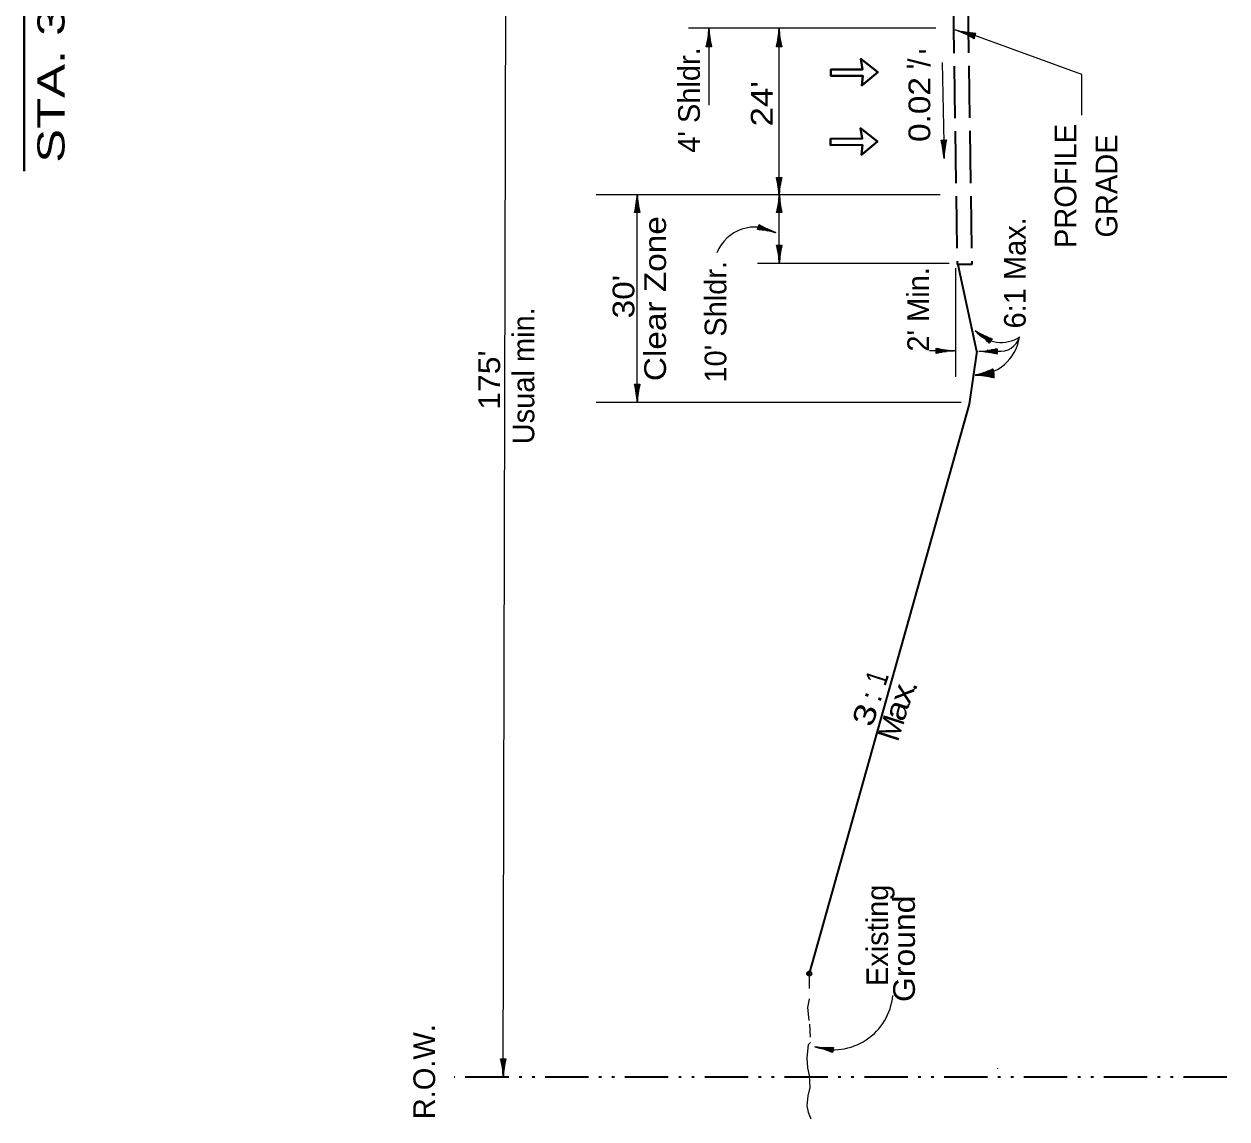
# Model space of a CAD drawing. Extents: x 2363427 to 2368559, y 6957299 to 6980140.
# Drawn here: x 2364444 to 2365220, y 6962821 to 6963528 of the extents above; entities that cross this region are included whole.
import ezdxf
from ezdxf.enums import TextEntityAlignment as Align

# ---------------------------------------------------------------- set-up
doc = ezdxf.new("R2010")
doc.units = 0
doc.header["$LTSCALE"] = 5.6
doc.header["$PDMODE"] = 32
doc.header["$PDSIZE"] = 2.8
for name, pattern in [('DASH_DOUBLE_DOT', [9.2, 5, -1.2, 0.3, -1.2, 0.3, -1.2]), ('LONG_DASHED', [7.5, 6, -1.5]), ('SHORT_DASHED', [2.7, 1.5, -1.2])]:
    doc.linetypes.add(name, pattern=pattern)
for name, color, linetype, lineweight in [('1', 7, 'Continuous', 13), ('3', 7, 'Continuous', 35), ('4', 7, 'Continuous', 13), ('40', 7, 'Continuous', 35), ('6', 7, 'Continuous', 13), ('8', 7, 'Continuous', 13)]:
    doc.layers.add(name, color=color, linetype=linetype, lineweight=lineweight)

msp = doc.modelspace()

# ---------------------------------------------------------------- linework, layer by layer
at = {"layer": '1', "lineweight": 35}
msp.add_line((2364985.047, 6963494.291), (2364964.542, 6963494.096), dxfattribs=at)
at = {"layer": '1'}
for p, q in [((2364965.957, 6962865.397), (2364954.863, 6962867.385)), ((2364965.877, 6962864.956), (2364958.275, 6962866.317)), ((2364966.035, 6962865.839), (2364959.546, 6962867.001)), ((2364965.798, 6962864.515), (2364961.505, 6962865.283)), ((2364966.115, 6962866.281), (2364962.339, 6962866.957)), ((2364965.719, 6962864.073), (2364963.616, 6962864.45)), ((2364966.193, 6962866.722), (2364964.794, 6962866.973)), ((2364966.249, 6962867.031), (2364965.643, 6962863.649))]:
    msp.add_line(p, q, dxfattribs=at)
at = {"layer": '1', "linetype": 'LONG_DASHED'}
msp.add_line((2365071.963, 6962853.593), (2365072.008, 6962853.139), dxfattribs=at)
at = {"layer": '1'}
msp.add_lwpolyline([(2365126.534, 6963468.759), (2365126.534, 6963495.013), (2365057.512, 6963520.217)], dxfattribs=at)
at = {"layer": '1', "lineweight": 40}
msp.add_lwpolyline([(2364994.902, 6963496.511), (2364984.515, 6963487.976), (2364985.047, 6963494.291), (2364964.542, 6963494.096), (2364964.505, 6963498.191), (2364985.009, 6963498.386), (2364983.802, 6963505.114)], close=True, dxfattribs=at)
at = {"layer": '1', "lineweight": 35}
for points in [[(2364985.047, 6963494.291), (2364984.515, 6963487.976), (2364994.902, 6963496.511), (2364983.802, 6963505.114), (2364985.009, 6963498.386)], [(2364985.009, 6963498.386), (2364964.505, 6963498.191), (2364964.542, 6963494.096)]]:
    msp.add_lwpolyline(points, dxfattribs=at)
at = {"layer": '1', "linetype": 'SHORT_DASHED'}
msp.add_lwpolyline([(2364950.389, 6962913.532), (2364950.389, 6962898.17), (2364949.462, 6962892.719), (2364950.622, 6962882.065), (2364951.317, 6962870.171), (2364949.926, 6962868.684), (2364948.998, 6962860.013), (2364949.462, 6962853.818), (2364950.389, 6962848.862), (2364950.853, 6962841.181), (2364949.694, 6962835.73), (2364948.998, 6962829.288), (2364949.926, 6962825.324), (2364951.549, 6962820.863)], dxfattribs=at)
at = {"layer": '1'}
for centre, radius, start, end in [((2364966.202, 6962903.94), 38.392, 251.77717, 354.885), ((2364962.433, 6962931.694), 64.775, 262.69085, 273.3769), ((2364939.626, 6962804.33), 64.775, 66.31768, 77.00373)]:
    msp.add_arc(centre, radius, start, end, dxfattribs=at)
at = {"layer": '3', "linetype": 'LONG_DASHED'}
for p, q in [((2365043.402, 6963542.525), (2365045.951, 6963372.457)), ((2365052.887, 6963542.605), (2365055.437, 6963372.518)), ((2365055.439, 6963372.342), (2365046.071, 6963372.342))]:
    msp.add_line(p, q, dxfattribs=at)
at = {"layer": '3', "lineweight": 13}
for p, q in [((2365032.339, 6963524.951), (2364872.566, 6963524.951)), ((2365036.402, 6963502.744), (2365037.537, 6963440.864)), ((2365035.601, 6963452.77), (2365039.035, 6963452.834)), ((2365035.915, 6963452.776), (2365035.94, 6963451.355)), ((2365036.363, 6963452.784), (2365036.433, 6963448.949)), ((2365036.812, 6963452.792), (2365036.932, 6963446.201)), ((2365037.26, 6963452.801), (2365037.467, 6963441.533)), ((2365037.708, 6963452.809), (2365037.85, 6963445.087)), ((2365038.157, 6963452.817), (2365038.237, 6963448.457)), ((2365038.605, 6963452.825), (2365038.644, 6963450.689)), ((2365035.153, 6963417.311), (2364813.061, 6963417.311)), ((2365040.909, 6963372.961), (2364917.115, 6963372.961)), ((2365048.541, 6963283.261), (2364813.015, 6963283.261))]:
    msp.add_line(p, q, dxfattribs=at)
at = {"layer": '3'}
for p, q in [((2365046.377, 6963372.422), (2365058.549, 6963316.426)), ((2365058.62, 6963316.451), (2365053.733, 6963282.354)), ((2365053.733, 6963282.354), (2364950.542, 6962914.671))]:
    msp.add_line(p, q, dxfattribs=at)
at = {"layer": '3', "linetype": 'DASH_DOUBLE_DOT'}
msp.add_line((2365220.18, 6962847.815), (2364721.247, 6962847.815), dxfattribs=at)
at = {"layer": '3', "lineweight": 13}
for centre, start, end in [((2364972.913, 6963436.464), 3.89448, 14.58053), ((2365102.28, 6963438.837), 167.52132, 178.20737)]:
    msp.add_arc(centre, 64.775, start, end, dxfattribs=at)
at = {"layer": '3'}
msp.add_point((2364950.542, 6962914.671), dxfattribs=at)
at = {"layer": '4', "lineweight": 40}
msp.add_line((2364443.654, 6963432.577), (2364443.654, 6963890.617), dxfattribs=at)
at = {"layer": '4'}
for p, q in [((2365057.487, 6963519.925), (2365045.464, 6963523.571)), ((2365057.632, 6963520.404), (2365049.393, 6963522.902)), ((2365057.342, 6963519.447), (2365050.309, 6963521.58)), ((2365057.197, 6963518.968), (2365053.105, 6963520.209)), ((2365057.777, 6963520.882), (2365053.125, 6963522.293)), ((2365057.923, 6963521.361), (2365055.643, 6963522.052)), ((2365056.951, 6963518.155), (2365058.061, 6963521.82)), ((2365057.052, 6963518.49), (2365055.535, 6963518.95)), ((2364930.83, 6963405.871), (2364930.83, 6963413.593)), ((2364931.279, 6963405.871), (2364931.279, 6963417.141)), ((2364931.727, 6963405.871), (2364931.727, 6963412.463)), ((2364932.938, 6963405.871), (2364929.502, 6963405.871)), ((2364929.933, 6963405.871), (2364929.933, 6963408.007)), ((2364930.381, 6963405.871), (2364930.381, 6963410.231)), ((2364932.175, 6963405.871), (2364932.175, 6963409.707)), ((2364932.624, 6963405.871), (2364932.624, 6963407.293)), ((2364917.149, 6963394.969), (2364918.195, 6963398.242)), ((2364917.518, 6963396.123), (2364923.798, 6963394.117)), ((2364917.655, 6963396.55), (2364928.39, 6963393.121)), ((2364917.791, 6963396.977), (2364925.147, 6963394.627)), ((2364917.927, 6963397.405), (2364922.082, 6963396.077)), ((2364918.064, 6963397.832), (2364920.099, 6963397.181)), ((2364917.245, 6963395.269), (2364918.599, 6963394.835)), ((2364917.381, 6963395.695), (2364921.035, 6963394.529)), ((2364929.502, 6963384.901), (2364932.938, 6963384.901)), ((2364929.502, 6963384.901), (2364932.938, 6963384.901)), ((2364929.816, 6963384.901), (2364929.816, 6963383.479)), ((2364929.816, 6963384.901), (2364929.816, 6963383.479)), ((2364930.265, 6963384.901), (2364930.265, 6963381.065)), ((2364930.265, 6963384.901), (2364930.265, 6963381.065)), ((2364930.713, 6963384.901), (2364930.713, 6963378.309)), ((2364930.713, 6963384.901), (2364930.713, 6963378.309)), ((2364931.161, 6963384.901), (2364931.161, 6963373.631)), ((2364931.161, 6963384.901), (2364931.161, 6963373.631)), ((2364931.61, 6963384.901), (2364931.61, 6963377.179)), ((2364931.61, 6963384.901), (2364931.61, 6963377.179)), ((2364932.059, 6963384.901), (2364932.059, 6963380.541)), ((2364932.059, 6963384.901), (2364932.059, 6963380.541)), ((2364932.507, 6963384.901), (2364932.507, 6963382.765)), ((2364932.507, 6963384.901), (2364932.507, 6963382.765)), ((2365044.903, 6963370.073), (2365044.903, 6963299.831)), ((2365067.734, 6963323.028), (2365058.294, 6963329.183)), ((2365067.489, 6963322.652), (2365061.02, 6963326.87)), ((2365067.979, 6963323.405), (2365062.457, 6963327.005)), ((2365032.48, 6963315.061), (2365032.48, 6963318.497)), ((2365067.245, 6963322.277), (2365063.591, 6963324.659)), ((2365068.224, 6963323.78), (2365065.011, 6963325.874)), ((2365066.999, 6963321.901), (2365065.21, 6963323.068)), ((2365068.64, 6963324.419), (2365066.764, 6963321.54)), ((2365068.469, 6963324.155), (2365067.278, 6963324.932)), ((2365044.421, 6963316.779), (2365028.191, 6963316.779)), ((2365032.48, 6963318.066), (2365034.617, 6963318.066)), ((2365032.48, 6963317.617), (2365036.841, 6963317.617)), ((2365032.48, 6963317.169), (2365040.203, 6963317.169)), ((2365032.48, 6963316.721), (2365043.75, 6963316.721)), ((2365032.48, 6963316.272), (2365039.073, 6963316.272)), ((2365032.48, 6963315.823), (2365036.316, 6963315.823)), ((2365032.48, 6963315.375), (2365033.902, 6963315.375)), ((2365071.895, 6963316.341), (2365060.625, 6963316.341)), ((2365071.895, 6963315.893), (2365064.172, 6963315.893)), ((2365071.895, 6963316.79), (2365065.302, 6963316.79)), ((2365071.895, 6963315.445), (2365067.534, 6963315.445)), ((2365071.895, 6963317.239), (2365068.059, 6963317.239)), ((2365071.895, 6963314.996), (2365069.759, 6963314.996)), ((2365071.895, 6963317.687), (2365070.473, 6963317.687)), ((2365071.895, 6963318.001), (2365071.895, 6963314.565)), ((2365069.374, 6963303.459), (2365058.353, 6963301.105)), ((2365069.467, 6963303.02), (2365061.915, 6963301.407)), ((2365069.28, 6963303.898), (2365062.832, 6963302.521)), ((2365069.186, 6963304.337), (2365065.435, 6963303.536)), ((2365069.093, 6963304.775), (2365067.702, 6963304.478)), ((2365069.027, 6963305.082), (2365069.745, 6963301.722)), ((2365069.644, 6963300.921), (2365058.374, 6963300.991)), ((2365069.641, 6963300.473), (2365061.919, 6963300.521)), ((2365069.647, 6963301.37), (2365063.054, 6963301.411)), ((2365069.639, 6963300.024), (2365065.277, 6963300.051)), ((2365069.561, 6963302.582), (2365065.296, 6963301.671)), ((2365069.65, 6963301.818), (2365065.813, 6963301.842)), ((2365069.635, 6963299.576), (2365067.499, 6963299.589)), ((2365069.655, 6963302.144), (2365067.566, 6963301.697)), ((2365069.653, 6963302.267), (2365068.231, 6963302.276)), ((2365069.654, 6963302.581), (2365069.633, 6963299.145))]:
    msp.add_line(p, q, dxfattribs=at)
for centre, radius, start, end in [((2365062.269, 6963593.91), 72.212, 255.97422, 266.66027), ((2365020.41, 6963455.87), 72.212, 59.60106, 70.28711), ((2364866.525, 6963421.025), 64.775, 346.47039, 357.15644), ((2364995.915, 6963421.025), 64.775, 182.84356, 193.52961), ((2364915.574, 6963369.999), 26.583, 59.62074, 157.81619), ((2364951.795, 6963453.621), 64.775, 238.75343, 249.43948), ((2364912.42, 6963330.368), 64.775, 75.12659, 85.81264), ((2364866.525, 6963369.748), 64.775, 2.84356, 13.52961), ((2364866.525, 6963369.748), 64.775, 2.84356, 13.52961), ((2364995.915, 6963369.748), 64.775, 166.47039, 177.15644), ((2364995.915, 6963369.748), 64.775, 166.47039, 177.15644), ((2365019.674, 6963277.063), 64.775, 43.36544, 54.05149), ((2365090.344, 6963385.449), 64.775, 239.73861, 250.42466), ((2365074.323, 6963344.391), 22.29, 221.78861, 303.3609), ((2365047.634, 6963381.474), 64.775, 256.47039, 267.15644), ((2365057.88, 6963329.594), 28.657, 269.64759, 351.5817), ((2365073.976, 6963329.264), 12.846, 261.86643, 343.6214), ((2365047.634, 6963252.085), 64.775, 92.84356, 103.52961), ((2365056.741, 6963380.978), 64.775, 272.84356, 283.52961), ((2365056.741, 6963251.589), 64.775, 76.47039, 87.15644), ((2365041.051, 6963363.504), 64.775, 284.90306, 295.58911), ((2365054.888, 6963365.65), 64.775, 272.49115, 283.1772), ((2365054.093, 6963236.263), 64.775, 76.11798, 86.80403), ((2365068.084, 6963236.97), 64.775, 88.52989, 99.21594)]:
    msp.add_arc(centre, radius, start, end, dxfattribs=at)
at = {"layer": '40'}
msp.add_line((2364984.806, 6963449.553), (2364964.301, 6963449.358), dxfattribs=at)
for points in [[(2364984.806, 6963449.553), (2364984.273, 6963443.238), (2364994.661, 6963451.773), (2364983.561, 6963460.376), (2364984.769, 6963453.648)], [(2364984.769, 6963453.648), (2364964.263, 6963453.453), (2364964.301, 6963449.358)]]:
    msp.add_lwpolyline(points, dxfattribs=at)
at = {"layer": '6'}
for p, q in [((2364753.047, 6962847.815), (2364754.869, 6963632.964)), ((2364885.423, 6963513.011), (2364885.423, 6963520.733)), ((2364885.813, 6963524.951), (2364885.813, 6963475.257)), ((2364885.871, 6963513.011), (2364885.871, 6963524.281)), ((2364930.65, 6963513.011), (2364930.65, 6963520.733)), ((2364931.04, 6963416.577), (2364931.04, 6963524.951)), ((2364931.099, 6963513.011), (2364931.099, 6963524.281)), ((2364887.53, 6963513.011), (2364884.095, 6963513.011)), ((2364884.526, 6963513.011), (2364884.526, 6963515.147)), ((2364884.974, 6963513.011), (2364884.974, 6963517.372)), ((2364886.32, 6963513.011), (2364886.32, 6963519.604)), ((2364886.768, 6963513.011), (2364886.768, 6963516.847)), ((2364887.217, 6963513.011), (2364887.217, 6963514.433)), ((2364932.758, 6963513.011), (2364929.322, 6963513.011)), ((2364929.753, 6963513.011), (2364929.753, 6963515.147)), ((2364930.201, 6963513.011), (2364930.201, 6963517.371)), ((2364931.547, 6963513.011), (2364931.547, 6963519.603)), ((2364931.995, 6963513.011), (2364931.995, 6963516.847)), ((2364932.444, 6963513.011), (2364932.444, 6963514.433)), ((2364929.322, 6963428.517), (2364932.758, 6963428.517)), ((2364929.322, 6963428.517), (2364932.758, 6963428.517)), ((2364929.636, 6963428.517), (2364929.636, 6963427.095)), ((2364929.636, 6963428.517), (2364929.636, 6963427.095)), ((2364930.085, 6963428.517), (2364930.085, 6963424.681)), ((2364930.085, 6963428.517), (2364930.085, 6963424.681)), ((2364930.533, 6963428.517), (2364930.533, 6963421.925)), ((2364930.533, 6963428.517), (2364930.533, 6963421.925)), ((2364930.981, 6963428.517), (2364930.981, 6963417.247)), ((2364930.981, 6963428.517), (2364930.981, 6963417.247)), ((2364931.43, 6963428.517), (2364931.43, 6963420.795)), ((2364931.43, 6963428.517), (2364931.43, 6963420.795)), ((2364931.879, 6963428.517), (2364931.879, 6963424.157)), ((2364931.879, 6963428.517), (2364931.879, 6963424.157)), ((2364932.327, 6963428.517), (2364932.327, 6963426.381)), ((2364932.327, 6963428.517), (2364932.327, 6963426.381)), ((2364839.076, 6963405.871), (2364839.076, 6963413.593)), ((2364839.466, 6963283.261), (2364839.466, 6963417.811)), ((2364839.525, 6963405.871), (2364839.525, 6963417.141)), ((2364839.973, 6963405.871), (2364839.973, 6963412.463)), ((2364931.22, 6963372.961), (2364931.22, 6963417.811)), ((2364841.184, 6963405.871), (2364837.748, 6963405.871)), ((2364838.179, 6963405.871), (2364838.179, 6963408.007)), ((2364838.627, 6963405.871), (2364838.627, 6963410.231)), ((2364840.421, 6963405.871), (2364840.421, 6963409.707)), ((2364840.87, 6963405.871), (2364840.87, 6963407.293)), ((2364837.748, 6963295.201), (2364841.184, 6963295.201)), ((2364838.062, 6963295.201), (2364838.062, 6963293.779)), ((2364838.511, 6963295.201), (2364838.511, 6963291.365)), ((2364838.959, 6963295.201), (2364838.959, 6963288.609)), ((2364839.407, 6963295.201), (2364839.407, 6963283.931)), ((2364839.856, 6963295.201), (2364839.856, 6963287.479)), ((2364840.305, 6963295.201), (2364840.305, 6963290.841)), ((2364840.753, 6963295.201), (2364840.753, 6963293.065)), ((2364751.328, 6962859.755), (2364754.764, 6962859.755)), ((2364751.642, 6962859.755), (2364751.642, 6962858.333)), ((2364752.091, 6962859.755), (2364752.091, 6962855.919)), ((2364752.539, 6962859.755), (2364752.539, 6962853.163)), ((2364752.987, 6962859.755), (2364752.987, 6962848.485)), ((2364753.436, 6962859.755), (2364753.436, 6962852.033)), ((2364753.885, 6962859.755), (2364753.885, 6962855.395)), ((2364754.333, 6962859.755), (2364754.333, 6962857.619))]:
    msp.add_line(p, q, dxfattribs=at)
for centre, start, end in [((2364821.118, 6963528.165), 346.47039, 357.15644), ((2364950.508, 6963528.165), 182.84356, 193.52961), ((2364866.345, 6963528.165), 346.47039, 357.15644), ((2364995.735, 6963528.165), 182.84356, 193.52961), ((2364866.345, 6963413.364), 2.84356, 13.52961), ((2364866.345, 6963413.364), 2.84356, 13.52961), ((2364995.735, 6963413.364), 166.47039, 177.15644), ((2364995.735, 6963413.364), 166.47039, 177.15644), ((2364774.771, 6963421.025), 346.47039, 357.15644), ((2364904.161, 6963421.025), 182.84356, 193.52961), ((2364774.771, 6963280.048), 2.84356, 13.52961), ((2364904.161, 6963280.048), 166.47039, 177.15644), ((2364688.351, 6962844.602), 2.84356, 13.52961), ((2364817.741, 6962844.602), 166.47039, 177.15644)]:
    msp.add_arc(centre, 64.775, start, end, dxfattribs=at)
at = {"layer": '8', "lineweight": 40}
msp.add_lwpolyline([(2364994.661, 6963451.773), (2364984.273, 6963443.238), (2364984.806, 6963449.553), (2364964.301, 6963449.358), (2364964.263, 6963453.453), (2364984.769, 6963453.648), (2364983.561, 6963460.376)], close=True, dxfattribs=at)

# ---------------------------------------------------------------- texts
at = {"layer": '4'}
for s, height, rotation, width, p in [('STA. 300+00 TO STA. 335+75', 17.5, 90, 1.4, (2364469.779, 6963662.093)), ("24'", 14, 90, 1.2, (2364926.85, 6963476.175)), ('0.02', 14, 90, 1.15, (2365028.642, 6963472.462)), ('Clear Zone', 14, 90, 1.15, (2364858.043, 6963350.378)), ("30'", 14, 90, 1.15, (2364837.622, 6963351.662)), ("175'", 14, 90, 1.1, (2364750.967, 6963297.819)), ('1', 14, 72.101, 0.75, (2365000.878, 6963103.447)), ('x', 14, 72.101, 1.25, (2365017.126, 6963093.462)), ('3', 14, 72.101, 1.3, (2364993.174, 6963079.594)), ('a', 14, 72.101, 1.2, (2365013.474, 6963082.627)), ('Ground', 14, 90, 1.1, (2365018.739, 6962930.714))]:
    msp.add_text(s, height=height, rotation=rotation, dxfattribs=dict(at, width=width)).set_placement(p, align=Align.CENTER)
for s, rotation, p in [("4' Shldr.", 90, (2364879.911, 6963478.578)), ('/', 90, (2365028.642, 6963502.747)), ("'", 90, (2365035.454, 6963509.924)), ("'", 90, (2365027.507, 6963500.217)), ('PROFILE', 90, (2365122.954, 6963423.111)), ('GRADE', 90, (2365149.454, 6963423.111)), ('6:1 Max.', 90, (2365090.274, 6963367.034)), ("10' Shldr.", 90, (2364897.031, 6963335.448)), ("2' Min.", 90, (2365027.847, 6963343.448)), ('Usual min.', 90, (2364773.027, 6963300.594)), (':', 72.101, (2364997.033, 6963091.545)), ('.', 72.101, (2365019.942, 6963099.171)), ('M', 72.101, (2365010.047, 6963071.169)), ('Existing ', 90, (2365001.475, 6962941.958)), ('R.O.W.', 90, (2364709.001, 6962851.362))]:
    msp.add_text(s, height=14, rotation=rotation, dxfattribs=at).set_placement(p, align=Align.CENTER)

doc.saveas('drawing.dxf')
